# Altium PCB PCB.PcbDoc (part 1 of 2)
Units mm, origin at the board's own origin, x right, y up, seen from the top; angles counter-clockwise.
Board outline 92.39 x 84.17 mm, 2 copper layers (Top Layer, Bottom Layer); 172 components, 86 nets, 462 pads, 473 vias.
Unrouted connection lines stored in the file: 353.
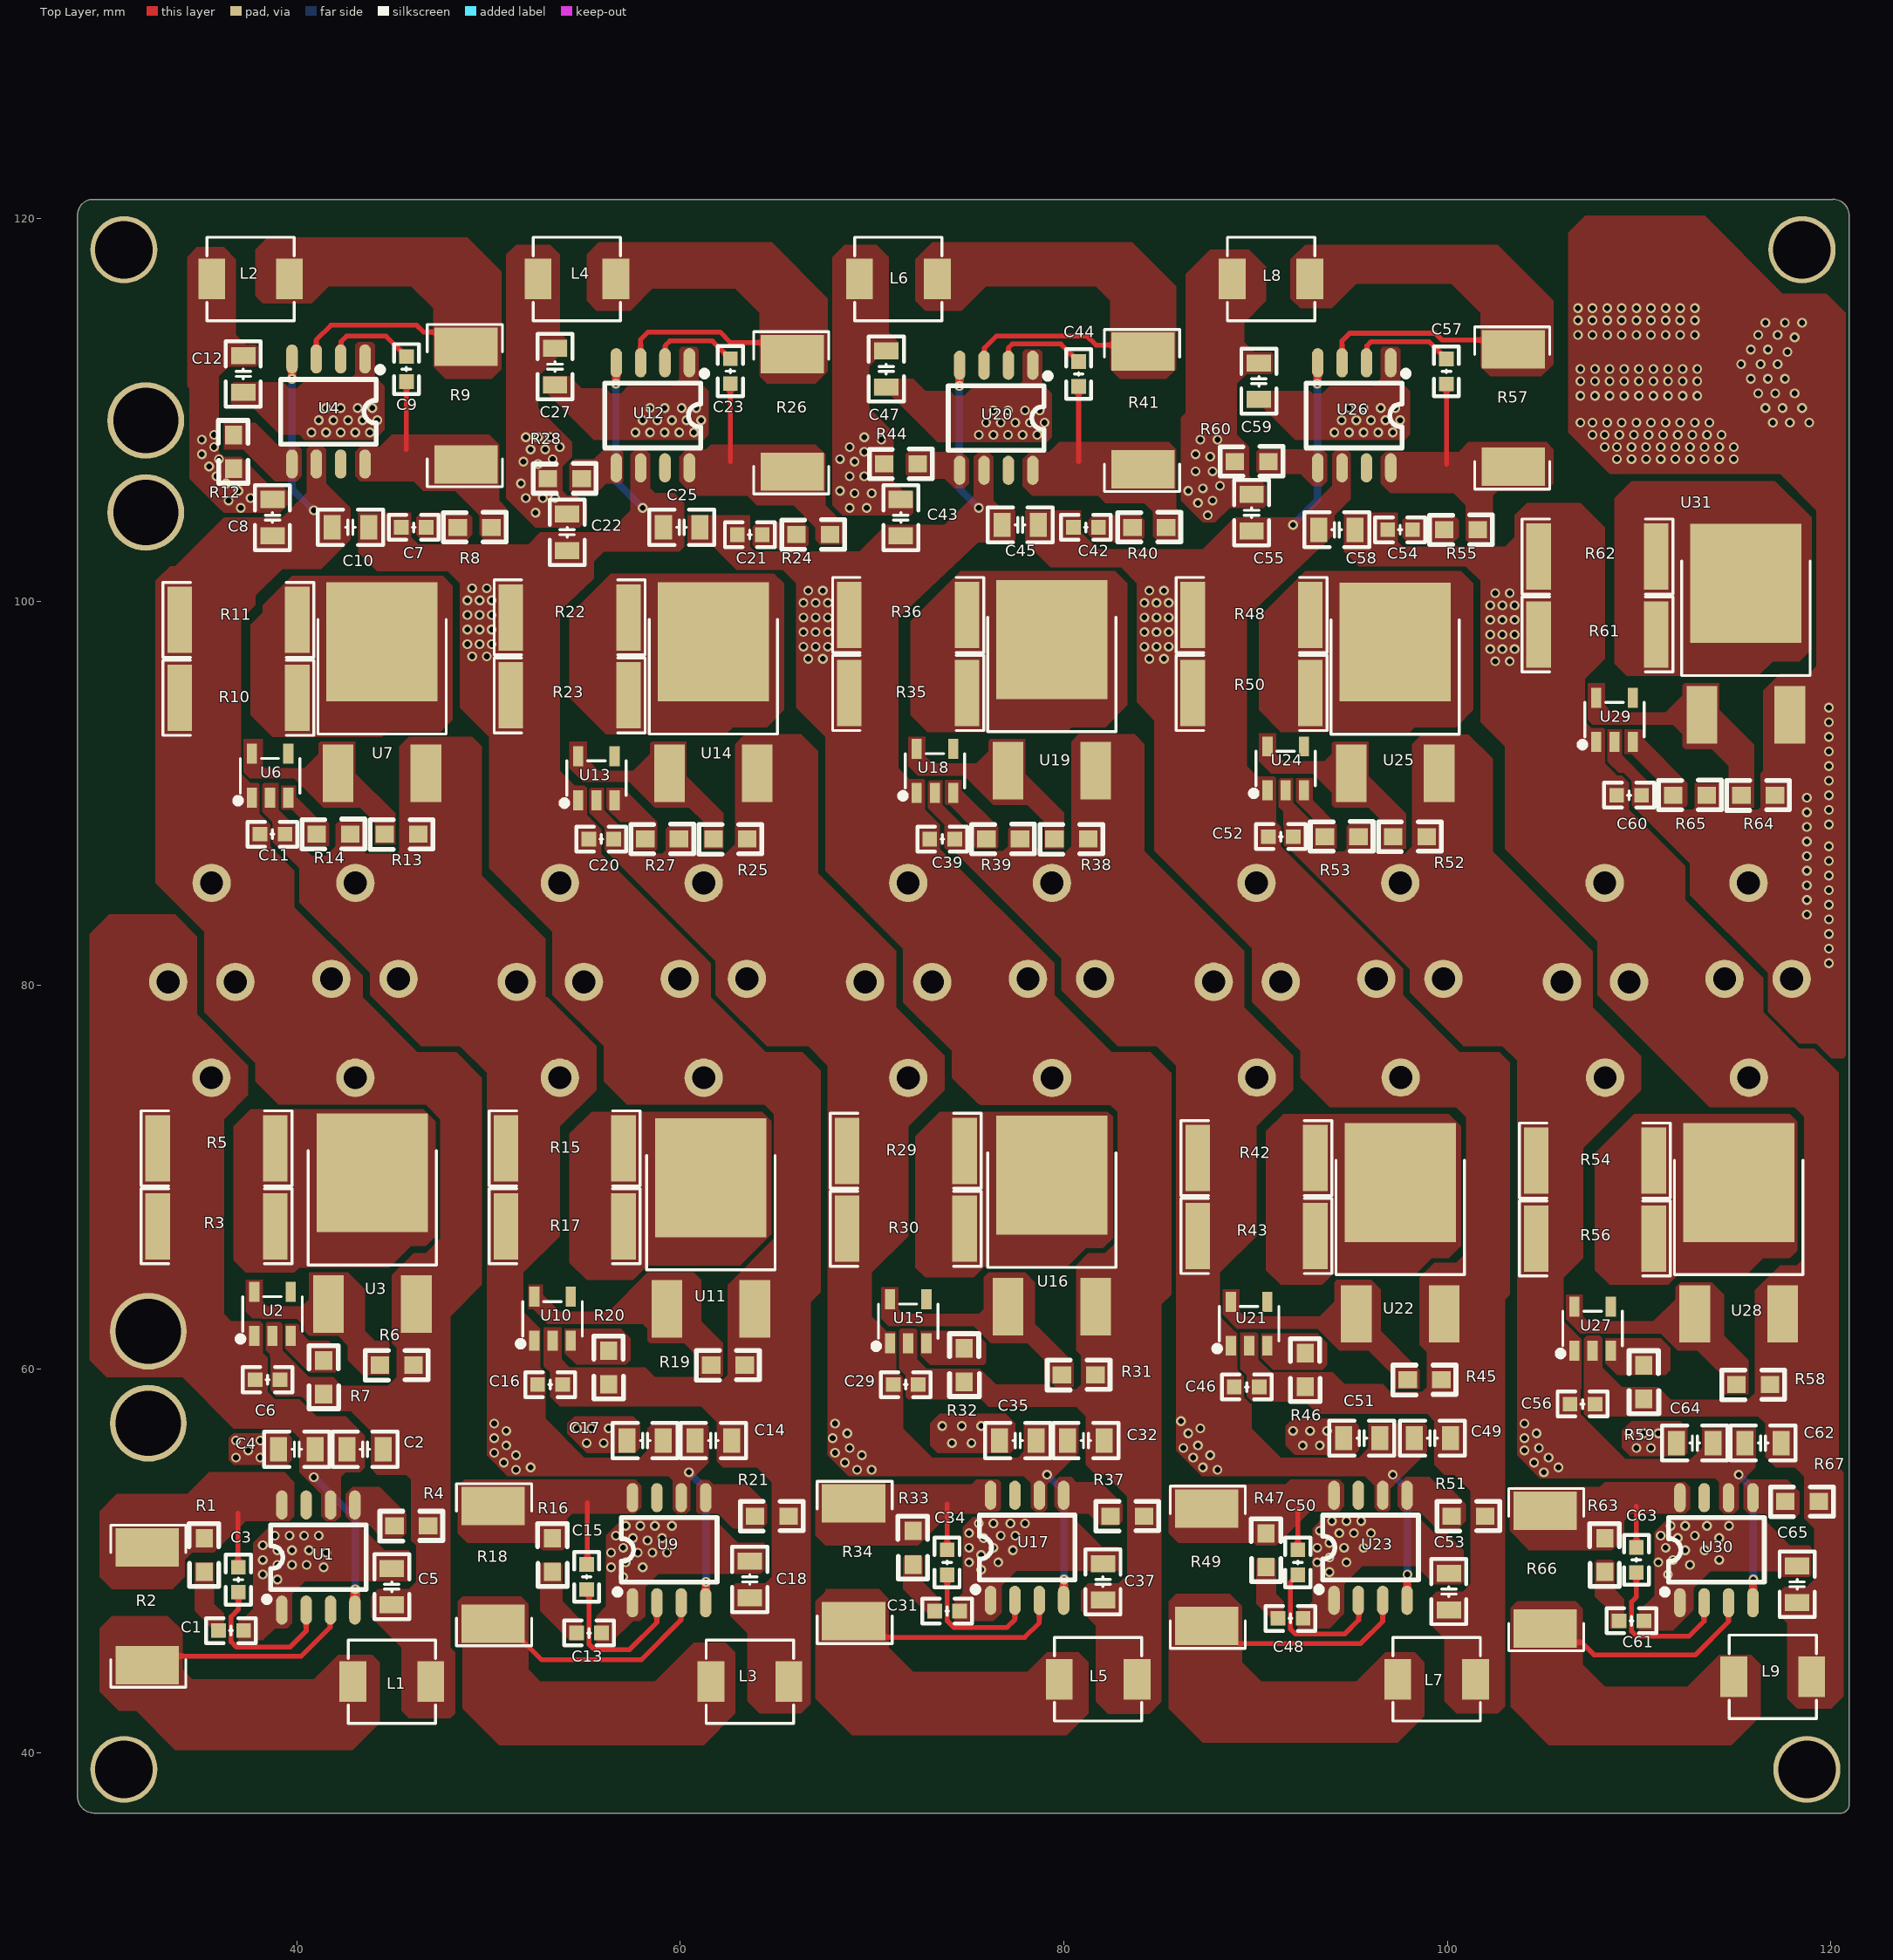
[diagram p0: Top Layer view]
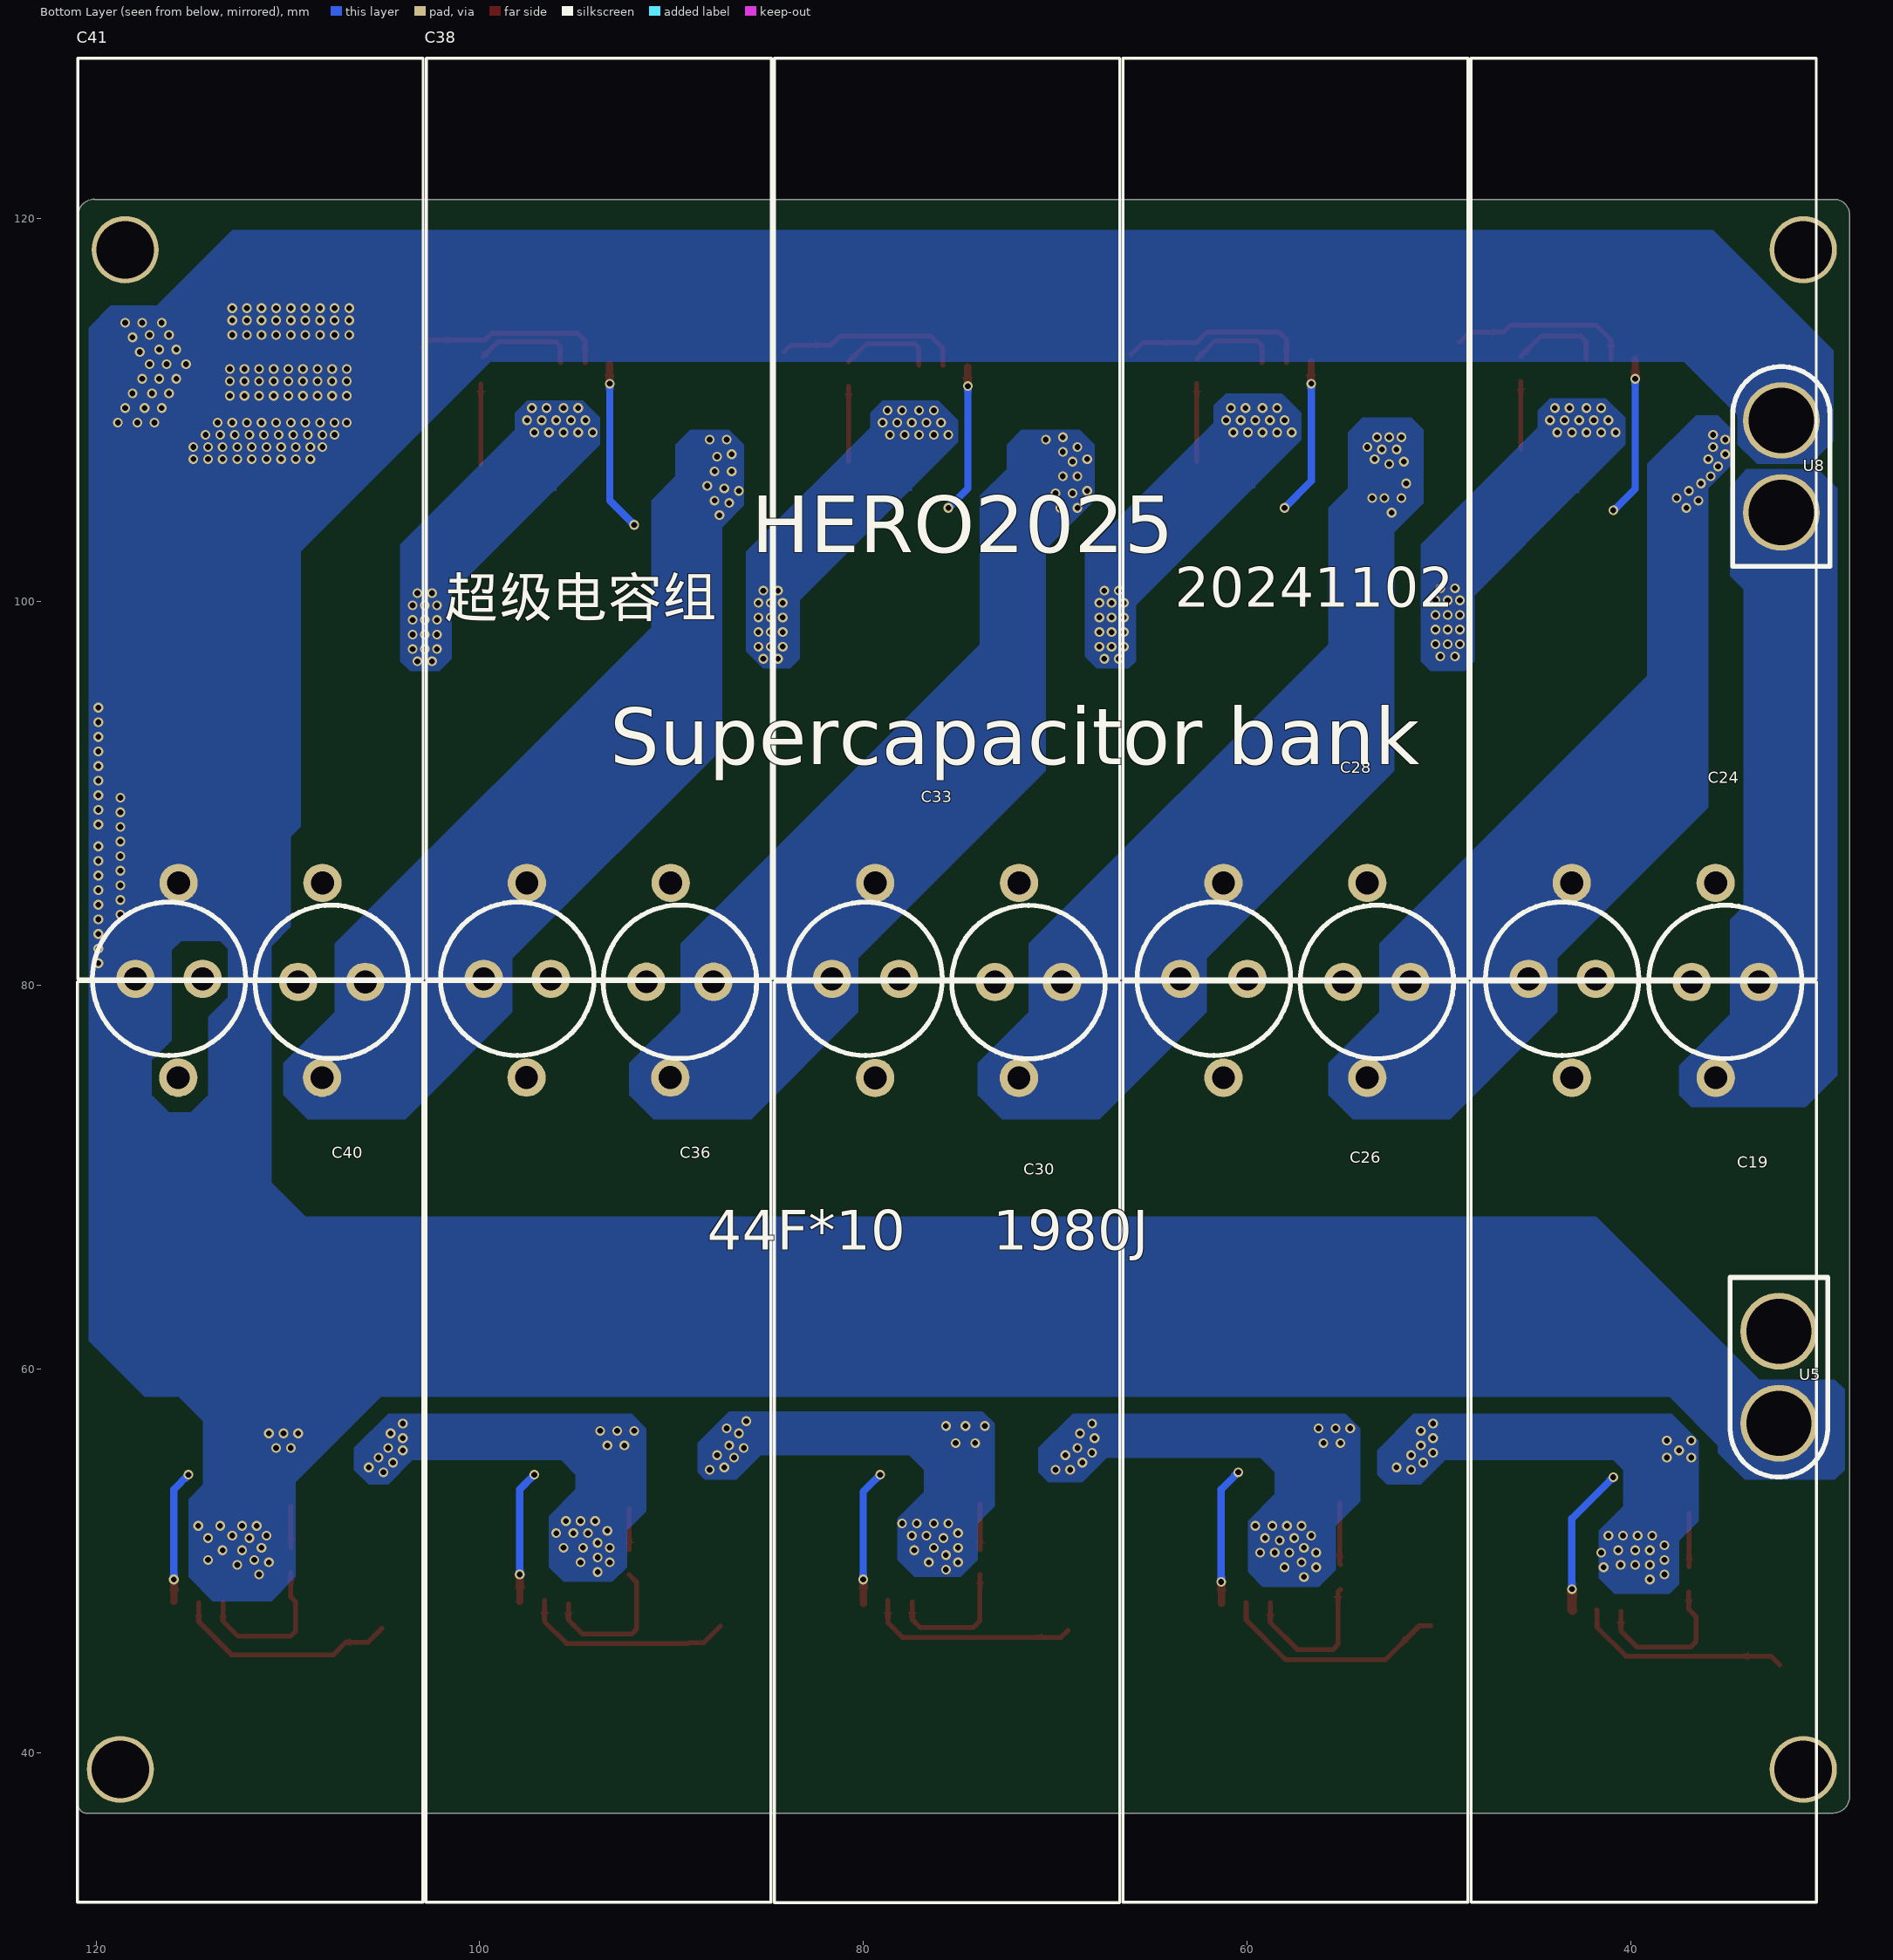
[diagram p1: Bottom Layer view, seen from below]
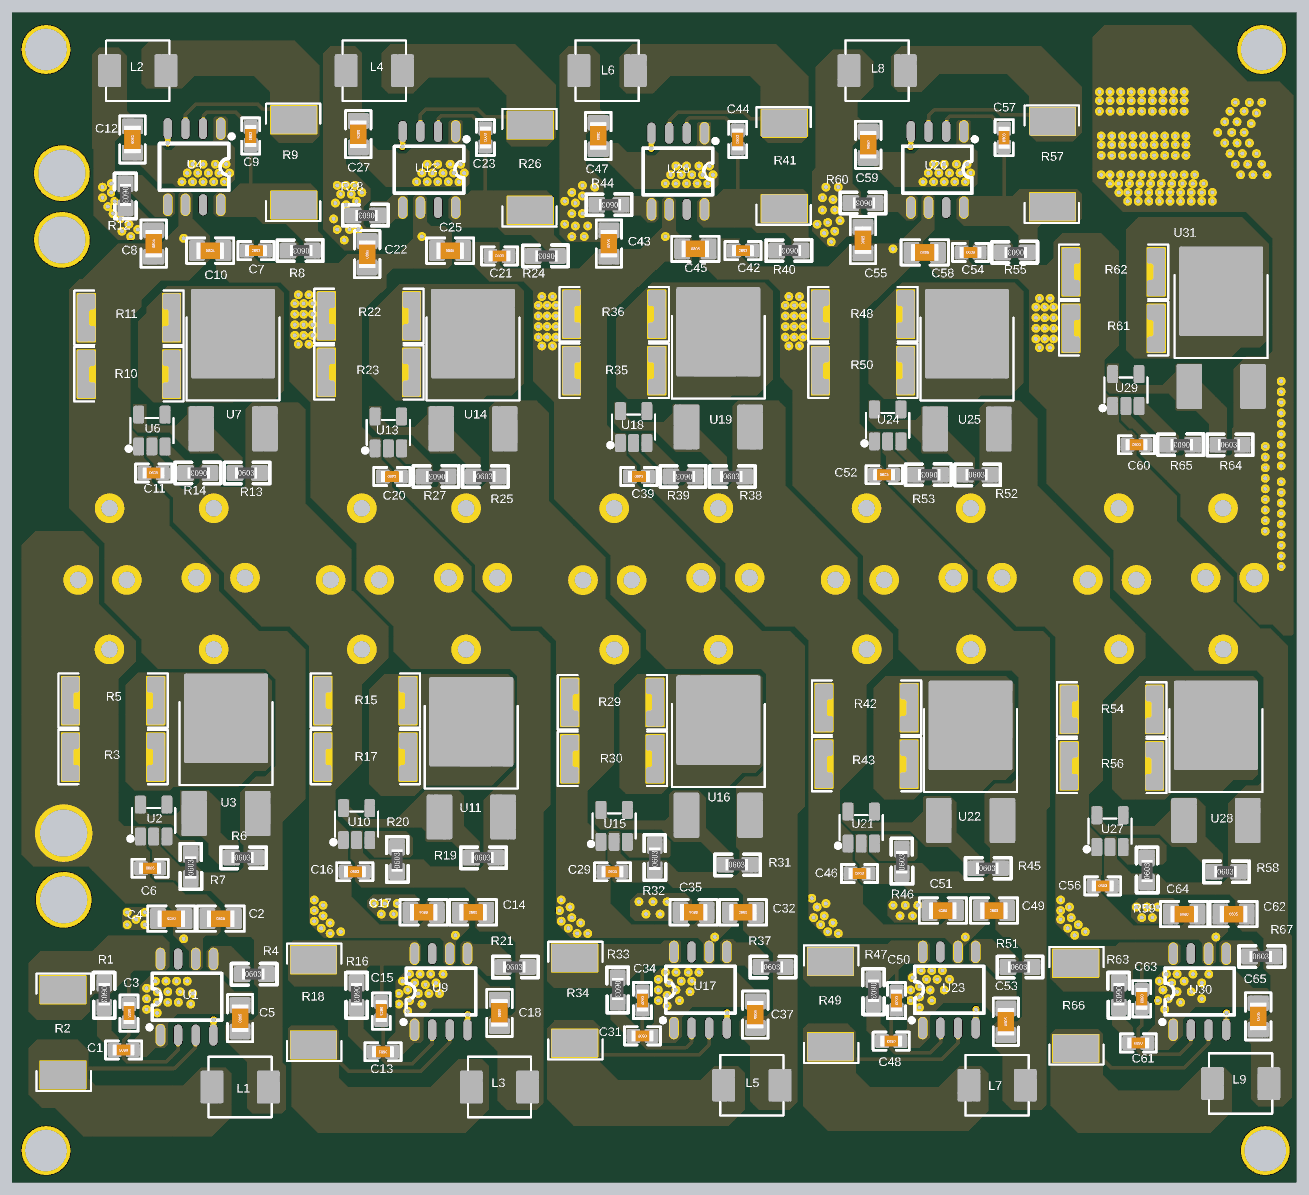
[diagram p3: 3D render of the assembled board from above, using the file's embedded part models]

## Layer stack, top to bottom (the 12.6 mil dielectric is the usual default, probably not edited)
Top Solder: solder mask 0.0102, Solder Resist, Dk 3.5
Top Layer: signal copper 0.0356
Dielectric 1: dielectric 0.32, FR-4, Dk 4.8
Bottom Layer: signal copper 0.0356
Bottom Solder: solder mask 0.0102, Solder Resist, Dk 3.5

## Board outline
28.57,37.731 28.57,120.188 28.575,120.142 cw(c29.377,120.186) 29.332,120.988 29.341,120.988 120.108,120.988 120.1,120.997 cw(c120.104,120.154) 120.946,120.158 120.953,120.189 120.961,37.319 cw(c120.468,37.32) 120.441,36.828 120.396,36.83 120.442,36.836 29.409,36.836 cw(c29.437,37.703)

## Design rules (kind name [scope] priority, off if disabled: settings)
Clearance [All] p1: gap=0.14 ignorepadtopadclearanceinfootprint=TRUE except(0.127: Arc-Arc Arc-Track Track-Track; 0.152: SMDPad-SMDPad SMDPad-THPad SMDPad-Via SMDPad-Fill SMDPad-Poly SMDPad-Region SMDPad-Text SMDPad-Hole THPad-THPad THPad-Via THPad-Fill THPad-Poly THPad-Region THPad-Text THPad-Hole Via-Via Via-Fill Via-Poly Via-Region Via-Text Via-Hole Fill-Hole Poly-Hole Region-Hole Text-Hole)
ComponentClearance [All] p1 off: gap=0.025 collisioncheckmode=3 verticalgap=0 showdistances=TRUE
DiffPairsRouting [All] p1: maxlimit=0.305 minlimit=0.203 mostfreqgap=0.254 toplayer_minwidth=0.203 toplayer_maxwidth=0.381 toplayer_prefwidth=0.254 bottomlayer_minwidth=0.203 bottomlayer_maxwidth=0.381 bottomlayer_prefwidth=0.254 maxuncoupledlength=12.7
HoleSize [All] p1: absolutevalues=TRUE maxlimit=40 minlimit=0.3 maxpercent=80.000 minpercent=20.000
MinimumSolderMaskSliver [All] p1: minsoldermaskwidth=0
NetAntennae [All] p1: netantennaetolerance=0.025
PasteMaskExpansion [All] p1: expansion=0.127
PlaneConnect [All] p1: planeconnectstyle=Direct reliefexpansion=0.508 reliefentries=4 reliefconductorwidth=0.635 reliefairgap=0.254
PolygonConnect [All] p1: connectstyle=Direct reliefconductorwidth=0.635 reliefentries=4 polygonreliefangle="90 Angle" airgapwidth=0.254
RoutingVias [All] p1: holewidth=0.508 width=0.889 viastyle="Through Hole" minholewidth=0.3 minwidth=0.6 maxholewidth=40 maxwidth=40.152
SilkToSilkClearance [All] p1: silktosilkclearance=0
SilkToSolderMaskClearance [IsPad] p1: minsilkscreentomaskgap=0 clearancetoexposedcopper=TRUE
SolderMaskExpansion [All] p1: expansion=0.064 istentingtop=FALSE
SupplyNets "Schematic Supply Nets_1" [InNet('GND')] p1: voltage=0.000
SupplyNets "Schematic Supply Nets" [InNet('PWR')] p2: voltage=0.000
Width [All] p1: maxlimit=3.175 minlimit=0.127 preferedwidth=0.508
21 further rules are at their usual default settings.

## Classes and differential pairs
component class "Room Definition5": C13 C14 C15 C16 C17 C18 L3 R15 R16 R17 R18 R19 R20 R21 U9 U10 U11
component class "Room Definition4": C20 C21 C22 C23 C25 C27 L4 R22 R23 R24 R25 R26 R27 R28 U12 U13 U14
component class "Room Definition3": C7 C8 C9 C10 C11 C12 L2 R8 R9 R10 R12 R13 R14 U4 U6 U7
component class "Room Definition2": C1 C2 C3 C4 C5 C6 L1 R1 R2 R3 R4 R5 R6 R7 U1 U2 U3
component class "Room Definition1": C1 C2 C3 C4 C5 L1 R1 R2 R4 U1

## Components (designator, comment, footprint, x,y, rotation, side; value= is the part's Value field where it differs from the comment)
C1 "2.2nF/0603" "C 0603_L" 36.576,46.355 r180 top
C2 "22uF/0805" "C 0805_L" 43.561,55.808 r0 top
C3 "100nF/0603" "C 0603_L" 36.957,49.007 r270 top
C4 "10uF/0805" "C 0805_L" 40.005,55.808 r180 top
C5 "22uF/0805" "C 0805_L" 44.958,48.641 r90 top
C6 "100nF/0603" "C 0603_L" 38.481,59.436 r0 top
C7 "2.2nF/0603" "C 0603_L" 46.101,103.886 r0 top
C8 "22uF/0805" "C 0805_L" 38.735,104.394 r90 top
C9 "100nF/0603" "C 0603_L" 45.72,112.141 r90 top
C10 "10uF/0805" "C 0805_L" 42.799,103.886 r0 top
C11 "100nF/0603" "C 0603_L" 38.735,87.884 r0 top
C12 "22uF/0805" "C 0805_L" 37.211,111.887 r270 top
C13 "2.2nF/0603" "C 0603_L" 55.245,46.228 r180 top
C14 "22uF/0805" "C 0805_L" 61.722,56.261 r0 top
C15 "100nF/0603" "C 0603_L" 55.118,49.149 r270 top
C16 "100nF/0603" "C 0603_L" 53.213,59.182 r0 top
C17 "10uF/0805" "C 0805_L" 58.166,56.261 r180 top
C18 "22uF/0805" "C 0805_L" 63.627,49.022 r90 top
C19 "3V/44F" cap 25.553,87.217 r0 bottom locked
C20 "100nF/0603" "C 0603_L" 55.88,87.63 r0 top
C21 "2.2nF/0603" "C 0603_L" 63.627,103.505 r0 top
C22 "22uF/0805" "C 0805_L" 54.102,103.632 r90 top
C23 "100nF/0603" "C 0603_L" 62.611,112.029 r90 top
C24 "3V/44F" cap 53.06,73.311 r180 bottom locked
C25 "10uF/0805" "C 0805_L" 60.071,103.886 r0 top
C26 "3V/44F" cap 43.721,87.217 r0 bottom locked
C27 "22uF/0805" "C 0805_L" 53.467,112.268 r270 top
C28 "3V/44F" cap 71.221,73.311 r180 bottom locked
C29 "100nF/0603" "C 0603_L" 71.755,59.182 r0 top
C30 "3V/44F" cap 61.887,87.205 r0 bottom locked
C31 "2.2nF/0603" "C 0603_L" 73.914,47.371 r180 top
C32 "22uF/0805" "C 0805_L" 81.153,56.261 r0 top
C33 "3V/44F" cap 89.382,73.311 r180 bottom locked
C34 "100nF/0603" "C 0603_L" 73.914,49.911 r270 top
C35 "10uF/0805" "C 0805_L" 77.597,56.261 r180 top
C36 "3V/44F" cap 80.064,87.222 r0 bottom locked
C37 "22uF/0805" "C 0805_L" 82.042,48.895 r90 top
C38 "3V/44F" cap 107.543,73.311 r180 bottom locked
C39 "100nF/0603" "C 0603_L" 73.66,87.63 r0 top
C40 "3V/44F" cap 98.225,87.219 r0 bottom locked
C41 "3V/44F" cap 125.704,73.311 r180 bottom locked
C42 "2.2nF/0603" "C 0603_L" 81.153,103.886 r0 top
C43 "22uF/0805" "C 0805_L" 71.501,104.394 r90 top
C44 "100nF/0603" "C 0603_L" 80.772,111.887 r90 top
C45 "10uF/0805" "C 0805_L" 77.724,104.013 r0 top
C46 "100nF/0603" "C 0603_L" 89.535,59.055 r0 top
C47 "22uF/0805" "C 0805_L" 70.739,112.141 r270 top
C48 "2.2nF/0603" "C 0603_L" 91.821,46.99 r180 top
C49 "22uF/0805" "C 0805_L" 99.218,56.388 r0 top
C50 "100nF/0603" "C 0603_L" 92.202,49.911 r270 top
C51 "10uF/0805" "C 0805_L" 95.535,56.388 r180 top
C52 "100nF/0603" "C 0603_L" 91.313,87.757 r0 top
C53 "22uF/0805" "C 0805_L" 100.076,48.387 r90 top
C54 "2.2nF/0603" "C 0603_L" 97.536,103.759 r0 top
C55 "22uF/0805" "C 0805_L" 89.789,104.648 r90 top
C56 "100nF/0603" "C 0603_L" 107.046,58.166 r0 top
C57 "100nF/0603" "C 0603_L" 99.949,112.014 r90 top
C58 "10uF/0805" "C 0805_L" 94.234,103.759 r0 top
C59 "22uF/0805" "C 0805_L" 90.17,111.506 r270 top
C60 "100nF/0603" "C 0603_L" 109.474,89.916 r0 top
C61 "2.2nF/0603" "C 0603_L" 109.601,46.863 r180 top
C62 "22uF/0805" "C 0805_L" 116.459,56.134 r0 top
C63 "100nF/0603" "C 0603_L" 109.855,50.038 r270 top
C64 "10uF/0805" "C 0805_L" 112.903,56.134 r180 top
C65 "22uF/0805" "C 0805_L" 118.237,48.768 r90 top
L1 "1uH" IND-SMD_L4.4-W4.2 44.958,43.688 r180 top
L2 "1uH" IND-SMD_L4.4-W4.2 37.592,116.84 r0 top
L3 "1uH" IND-SMD_L4.4-W4.2 63.627,43.688 r180 top
L4 "1uH" IND-SMD_L4.4-W4.2 54.61,116.84 r0 top
L5 "1uH" IND-SMD_L4.4-W4.2 81.788,43.815 r180 top
L6 "1uH" IND-SMD_L4.4-W4.2 71.374,116.84 r0 top
L7 "1uH" IND-SMD_L4.4-W4.2 99.441,43.815 r180 top
L8 "1uH" IND-SMD_L4.4-W4.2 90.805,116.84 r0 top
L9 "1uH" IND-SMD_L4.4-W4.2 116.967,43.942 r180 top
R1 "2.2/0603" "R 0603_L" 35.179,50.292 r270 top
R2 "100mΩ" RES-SMD_L6.4-W3.2-R2512 32.258,47.625 r270 top
R3 "4.7Ω/2512" R2512 35.814,67.437 r0 top value=4.7Ω
R4 "220/0603" "R 0603_L" 45.974,51.816 r0 top
R5 "4.7Ω/2512" R2512 35.814,71.501 r0 top value=4.7Ω
R6 "1k/0603" "R 0603_L" 45.212,60.198 r0 top
R7 "1k/0603" "R 0603_L" 41.402,59.563 r90 top
R8 "2.2/0603" "R 0603_L" 49.276,103.886 r180 top
R9 "100mΩ" RES-SMD_L6.4-W3.2-R2512 48.768,110.236 r90 top
R10 "4.7Ω/2512" R2512 36.957,94.996 r0 top value=4.7Ω
R11 "4.7Ω/2512" R2512 36.957,99.06 r0 top value=4.7Ω
R12 "220/0603" "R 0603_L" 36.703,107.823 r270 top
R13 "1k/0603" "R 0603_L" 45.466,87.884 r0 top
R14 "1k/0603" "R 0603_L" 41.91,87.884 r180 top
R15 "4.7Ω/2512" R2512 53.975,71.501 r0 top value=4.7Ω
R16 "2.2/0603" "R 0603_L" 53.34,50.292 r270 top
R17 "4.7Ω/2512" R2512 53.975,67.437 r0 top value=4.7Ω
R18 "100mΩ" RES-SMD_L6.4-W3.2-R2512 50.292,49.784 r270 top
R19 "1k/0603" "R 0603_L" 62.484,60.198 r0 top
R20 "1k/0603" "R 0603_L" 56.261,60.071 r90 top
R21 "220/0603" "R 0603_L" 64.77,52.324 r0 top
R22 "4.7Ω/2512" R2512 54.229,99.187 r0 top value=4.7Ω
R23 "4.7Ω/2512" R2512 54.229,95.123 r0 top value=4.7Ω
R24 "2.2/0603" "R 0603_L" 66.929,103.505 r180 top
R25 "1k/0603" "R 0603_L" 62.611,87.63 r0 top
R26 "100mΩ" RES-SMD_L6.4-W3.2-R2512 65.786,109.855 r90 top
R27 "1k/0603" "R 0603_L" 59.055,87.63 r180 top
R28 "220/0603" "R 0603_L" 53.975,106.426 r180 top
R29 "4.7Ω/2512" R2512 71.755,71.374 r0 top value=4.7Ω
R30 "4.7Ω/2512" R2512 71.755,67.31 r0 top value=4.7Ω
R31 "1k/0603" "R 0603_L" 80.772,59.69 r0 top
R32 "1k/0603" "R 0603_L" 74.803,60.198 r90 top
R33 "2.2/0603" "R 0603_L" 72.136,50.673 r270 top
R34 "100mΩ" RES-SMD_L6.4-W3.2-R2512 69.088,49.911 r270 top
R35 "4.7Ω/2512" R2512 71.882,95.25 r0 top value=4.7Ω
R36 "4.7Ω/2512" R2512 71.882,99.314 r0 top value=4.7Ω
R37 "220/0603" "R 0603_L" 83.312,52.324 r0 top
R38 "1k/0603" "R 0603_L" 80.391,87.63 r0 top
R39 "1k/0603" "R 0603_L" 76.835,87.63 r180 top
R40 "2.2/0603" "R 0603_L" 84.455,103.886 r180 top
R41 "100mΩ" RES-SMD_L6.4-W3.2-R2512 84.074,109.982 r90 top
R42 "4.7Ω/2512" R2512 90.043,70.993 r0 top value=4.7Ω
R43 "4.7Ω/2512" R2512 90.043,66.929 r0 top value=4.7Ω
R44 "220/0603" "R 0603_L" 71.501,107.188 r180 top
R45 "1k/0603" "R 0603_L" 98.806,59.436 r0 top
R46 "1k/0603" "R 0603_L" 92.583,59.944 r90 top
R47 "2.2/0603" "R 0603_L" 90.551,50.546 r270 top
R48 "4.7Ω/2512" R2512 89.789,99.314 r0 top value=4.7Ω
R49 "100mΩ" RES-SMD_L6.4-W3.2-R2512 87.503,49.657 r270 top
R50 "4.7Ω/2512" R2512 89.789,95.25 r0 top value=4.7Ω
R51 "220/0603" "R 0603_L" 101.092,52.324 r0 top
R52 "1k/0603" "R 0603_L" 98.044,87.757 r0 top
R53 "1k/0603" "R 0603_L" 94.488,87.757 r180 top
R54 "4.7Ω/2512" R2512 107.696,70.866 r0 top value=4.7Ω
R55 "2.2/0603" "R 0603_L" 100.711,103.759 r180 top
R56 "4.7Ω/2512" R2512 107.696,66.802 r0 top value=4.7Ω
R57 "100mΩ" RES-SMD_L6.4-W3.2-R2512 103.378,110.109 r90 top
R58 "1k/0603" "R 0603_L" 115.951,59.182 r0 top
R59 "1k/0603" "R 0603_L" 110.236,59.309 r90 top
R60 "220/0603" "R 0603_L" 89.789,107.315 r180 top
R61 "4.7Ω/2512" R2512 107.823,98.298 r0 top value=4.7Ω
R62 "4.7Ω/2512" R2512 107.823,102.362 r0 top value=4.7Ω
R63 "2.2/0603" "R 0603_L" 108.204,50.292 r270 top
R64 "1k/0603" "R 0603_L" 116.205,89.916 r0 top
R65 "1k/0603" "R 0603_L" 112.649,89.916 r180 top
R66 "100mΩ" RES-SMD_L6.4-W3.2-R2512 105.156,49.53 r270 top
R67 "220/0603" "R 0603_L" 118.491,53.086 r0 top
U1 "ETA3006S8A" SOIC-8_L5.0-W4.0-P1.27-LS6.0-TL 41.021,50.165 r90 top
U2 "BW6103" TSOT-23-5_L2.9-W1.6-P0.95-LS2.8-BL 38.735,62.865 r0 top
U3 "20N04" TO-252-2_L6.6-W6.1-P4.57-LS9.9-BR-CW 43.942,66.802 r270 top
U4 "ETA3006S8A" SOIC-8_L5.0-W4.0-P1.27-LS6.0-TL 41.763,109.928 r270 top
U5 "XT30U-F" CONN-TH_XT30U-F 32.258,59.563 r270 bottom
U6 "BW6103" TSOT-23-5_L2.9-W1.6-P0.95-LS2.8-BL 38.608,90.932 r0 top
U7 "20N04" TO-252-2_L6.6-W6.1-P4.57-LS9.9-BR-CW 44.45,94.488 r270 top
U8 "XT30U-F" CONN-TH_XT30U-F 32.131,107.061 r90 bottom
U9 "ETA3006S8A" SOIC-8_L5.0-W4.0-P1.27-LS6.0-TL 59.309,50.546 r90 top
U10 "BW6103" TSOT-23-5_L2.9-W1.6-P0.95-LS2.8-BL 53.34,62.611 r0 top
U11 "20N04" TO-252-2_L6.6-W6.1-P4.57-LS9.9-BR-CW 61.595,66.548 r270 top
U12 "ETA3006S8A" SOIC-8_L5.0-W4.0-P1.27-LS6.0-TL 58.674,109.728 r270 top
U13 "BW6103" TSOT-23-5_L2.9-W1.6-P0.95-LS2.8-BL 55.626,90.805 r0 top
U14 "20N04" TO-252-2_L6.6-W6.1-P4.57-LS9.9-BR-CW 61.722,94.488 r270 top
U15 "BW6103" TSOT-23-5_L2.9-W1.6-P0.95-LS2.8-BL 71.882,62.484 r0 top
U16 "20N04" TO-252-2_L6.6-W6.1-P4.57-LS9.9-BR-CW 79.375,66.675 r270 top
U17 "ETA3006S8A" SOIC-8_L5.0-W4.0-P1.27-LS6.0-TL 77.978,50.673 r90 top
U18 "BW6103" TSOT-23-5_L2.9-W1.6-P0.95-LS2.8-BL 73.279,91.186 r0 top
U19 "20N04" TO-252-2_L6.6-W6.1-P4.57-LS9.9-BR-CW 79.375,94.615 r270 top
U20 "ETA3006S8A" SOIC-8_L5.0-W4.0-P1.27-LS6.0-TL 76.581,109.601 r270 top
U21 "BW6103" TSOT-23-5_L2.9-W1.6-P0.95-LS2.8-BL 89.662,62.357 r0 top
U22 "20N04" TO-252-2_L6.6-W6.1-P4.57-LS9.9-BR-CW 97.536,66.294 r270 top
U23 "ETA3006S8A" SOIC-8_L5.0-W4.0-P1.27-LS6.0-TL 95.885,50.673 r90 top
U24 "BW6103" TSOT-23-5_L2.9-W1.6-P0.95-LS2.8-BL 91.567,91.313 r0 top
U25 "20N04" TO-252-2_L6.6-W6.1-P4.57-LS9.9-BR-CW 97.278,94.483 r270 top
U26 "ETA3006S8A" SOIC-8_L5.0-W4.0-P1.27-LS6.0-TL 95.25,109.728 r270 top
U27 "BW6103" TSOT-23-5_L2.9-W1.6-P0.95-LS2.8-BL 107.569,62.103 r0 top
U28 "20N04" TO-252-2_L6.6-W6.1-P4.57-LS9.9-BR-CW 115.189,66.294 r270 top
U29 "BW6103" TSOT-23-5_L2.9-W1.6-P0.95-LS2.8-BL 108.712,93.853 r0 top
U30 "ETA3006S8A" SOIC-8_L5.0-W4.0-P1.27-LS6.0-TL 113.919,50.546 r90 top
U31 "20N04" TO-252-2_L6.6-W6.1-P4.57-LS9.9-BR-CW 115.57,97.536 r270 top

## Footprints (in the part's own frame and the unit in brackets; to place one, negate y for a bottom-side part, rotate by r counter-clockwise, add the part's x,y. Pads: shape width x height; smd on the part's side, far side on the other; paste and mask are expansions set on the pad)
"C 0603_L" [mil] "无极性贴片电容"
  rect 30x30 smd: 1(-25.59,0) 2(25.59,0)
  silkscreen extent -51,-26 51,26, body extent -31,-16 31,16, height 32
"C 0805_L" [mil] "无极性贴片电容"
  rect 35x50 smd: 1(-37.4,0) 2(37.4,0)
  silkscreen extent -67,-36 67,36, body extent -39,-24 39,24, height 20
cap [mm]
  round 2 hole 1.2: 1(10,12.033) 2(17.5,12.033) 3(7.75,7.033) 4(11.25,7.033)
  silkscreen extent 4.75,3.03 22.75,55.03
CONN-TH_XT30U-F [mm]
  round 4 hole 3.4: 1(2.4,0) 2(-2.4,0)
  silkscreen extent -5.21,-2.54 5.2,2.54
IND-SMD_L4.4-W4.2 [mm]
  rect 1.4x2.12 smd: 1(2.028,0) 2(-2.028,0)
  silkscreen extent -2.28,-2.18 2.28,2.18
R2512 [mm]
  rect 1.283x3.456 smd paste-100 mask+0.051: 1(-3.066,0) 2(3.066,0)
  silkscreen extent -3.94,-1.96 3.94,1.96
"R 0603_L" [mil] "1/10W"
  rect 38x35 smd: 1(-34.5,0) 2(34.5,0)
  silkscreen extent -64,-31 64,30, body extent -34,-16 29,16, height 18
RES-SMD_L6.4-W3.2-R2512 [mm]
  rect 2x3.3 smd paste+0 mask+0.051: 1(-3.066,-0.052) 2(3.066,-0.052)
  silkscreen extent -4.23,-1.96 4.23,1.96
SOIC-8_L5.0-W4.0-P1.27-LS6.0-TL [mm]
  oval 1.52x0.6 smd paste+0 mask+0.051: 1(-2.74,1.798) 2(-2.74,0.528) 3(-2.74,-0.742) 4(-2.74,-2.012) 5(2.74,-2.012) 6(2.74,-0.742) 7(2.74,0.528) 8(2.74,1.798)
  silkscreen extent -2.33,-2.61 1.7,2.73
TO-252-2_L6.6-W6.1-P4.57-LS9.9-BR-CW [mm]
  rect 3x1.6 smd: 1(3.424,-2.29) 3(3.424,2.29)
  rect 6.2x5.8 smd: 2(-3.424,0)
  silkscreen extent -4.58,-3.35 1.38,3.35
TSOT-23-5_L2.9-W1.6-P0.95-LS2.8-BL [mm]
  rect 0.532x1.045 smd: 1(-0.95,-1.147) 2(0,-1.147) 3(0.95,-1.147) 4(0.95,1.147) 5(-0.95,1.147)
  silkscreen extent -1.82,-1.45 1.55,0.9

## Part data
C1 C2 C3 C4 C5 C6 C7 C8 C9 C10 C11 C12 C13 C14 C15 C16 C17 C18 C20 C21 C22 C23 C25 C27 C29 C31 C32 C34 C35 C37 C39 C42 C43 C44 C45 C46 C47 C48 C49 C50 C51 C52 C53 C54 C55 C56 C57 C58 C59 C60 C61 C62 C63 C64 C65: library part CAP, "陶瓷电容"
C19 C24 C26 C28 C30 C33 C36 C38 C40 C41: library part "3V 44F", "3V 40F 超级电容"
L1 L2 L3 L4 L5 L6 L7 L8 L9: library part FXL0420-1R0-M
R1 R4 R6 R7 R8 R12 R13 R14 R16 R19 R20 R21 R24 R25 R27 R28 R31 R32 R33 R37 R38 R39 R40 R44 R45 R46 R47 R51 R52 R53 R55 R58 R59 R60 R63 R64 R65 R67: library part RES, "贴片电阻"
R2 R9 R18 R26 R34 R41 R49 R57 R66: library part HOJLR2512-3W-100MR-1%
R3 R5 R10 R11 R15 R17 R22 R23 R29 R30 R35 R36 R42 R43 R48 R50 R54 R56 R61 R62: library part WF25P4R70FTL, "4.7Ω 2W", JLCPCB Part Class="Extended Part", LCSC Part Name="4.7Ω ±1% 2W", Manufacturer=Walsin(华新科), Operating Temperature Range=-55℃~+155℃, Overload Voltage (Max)=300V, Power(Watts)=2W, Temperature Coefficient=±100ppm/℃, Tolerance=±1%
U2 U6 U10 U13 U15 U18 U21 U24 U27 U29: "3V 均压保护芯片"
U3 U7 U11 U14 U16 U19 U22 U25 U28 U31: "40V 20A", Continuous Drain Current (Id)=20A, Drain Source On Resistance (RDS(on)@Vgs,Id)=25mΩ, Drain Source Voltage (Vdss)=40V, Gate Threshold Voltage (Vgs(th)@Id)=2.2V, LCSC Part Name="1个N沟道 耐压:40V 电流:20A", Manufacturer=HL(富海微)
U5 U8: Colour=黄色, contact resistance=-, JLCPCB Part Class="Extended Part", LCSC Part Name="AMASS(艾迈斯)轻量版锂电池插头母头 XT30U-F", Manufacturer=AMASS(艾迈斯)

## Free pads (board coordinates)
  round 3.5 hole 3: 7(30.988,39.116) 7(30.988,118.364) 7(118.491,118.364) 7(118.745,39.116)

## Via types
v1: diameter 0.508, hole 0.305, Top Layer to Bottom Layer, 473 vias

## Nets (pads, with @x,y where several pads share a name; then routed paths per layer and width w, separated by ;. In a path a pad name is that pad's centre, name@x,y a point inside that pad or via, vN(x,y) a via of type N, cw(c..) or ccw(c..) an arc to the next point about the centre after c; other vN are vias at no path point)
GND: C41.1 C41.3 C60.2 C61.1 C64.2 C65.2 R64.2 R65.1 U5.1 U8.1 U29.2 U30.1 U31.3
  other v1: 111.506,49.276 112.649,49.784 110.998,49.911 111.76,50.038 114.173,50.038 112.395,50.546 113.411,50.546 111.379,50.673 112.014,51.181 114.173,51.181 111.125,51.308 112.903,51.308 111.633,51.816 112.395,51.816 113.538,51.816 114.681,51.816 109.855,55.88 110.617,55.88 109.474,56.642 110.236,56.642 110.998,56.642 119.888,81.153 119.888,81.915 119.888,82.677 119.888,83.439 118.745,83.693 119.888,84.201 118.745,84.455 119.888,84.963 118.745,85.217 119.888,85.725 118.745,85.979 119.888,86.487 118.745,86.741 119.888,87.249 118.745,87.503 118.745,88.265 119.888,88.392 118.745,89.027 119.888,89.154 118.745,89.789 119.888,89.916 119.888,90.678 119.888,91.44 119.888,92.202 119.888,92.964 119.888,93.726 119.888,94.488 108.839,107.442 109.601,107.442 110.363,107.442 111.125,107.442 111.887,107.442 112.649,107.442 113.411,107.442 114.173,107.442 114.935,107.442 108.204,108.077 108.839,108.077 109.601,108.077 110.363,108.077 111.125,108.077 111.887,108.077 112.649,108.077 113.411,108.077 114.173,108.077 114.935,108.077 107.569,108.712 108.204,108.712 108.966,108.712 109.728,108.712 110.49,108.712 111.252,108.712 112.014,108.712 112.776,108.712 113.538,108.712 114.3,108.712 106.934,109.347 107.569,109.347 108.331,109.347 109.093,109.347 109.855,109.347 110.617,109.347 111.379,109.347 112.141,109.347 112.903,109.347 113.665,109.347 116.967,109.347 117.856,109.347 118.872,109.347 116.586,110.109 117.475,110.109 118.491,110.109 106.934,110.744 107.696,110.744 108.458,110.744 109.22,110.744 109.982,110.744 110.744,110.744 111.506,110.744 112.268,110.744 113.03,110.744 116.205,110.871 117.094,110.871 118.11,110.871 106.934,111.506 107.696,111.506 108.458,111.506 109.22,111.506 109.982,111.506 110.744,111.506 111.506,111.506 112.268,111.506 113.03,111.506 115.824,111.633 116.713,111.633 117.602,111.633 106.934,112.141 107.696,112.141 108.458,112.141 109.22,112.141 109.982,112.141 110.744,112.141 111.506,112.141 112.268,112.141 113.03,112.141 115.316,112.395 116.332,112.395 117.221,112.395 117.729,113.03 115.824,113.157 116.713,113.157 118.11,113.792 106.807,113.919 107.569,113.919 108.331,113.919 109.093,113.919 109.855,113.919 110.617,113.919 111.379,113.919 112.141,113.919 112.903,113.919 116.205,113.919 117.221,113.919 116.586,114.554 117.602,114.554 118.491,114.554 106.807,114.681 107.569,114.681 108.331,114.681 109.093,114.681 109.855,114.681 110.617,114.681 111.379,114.681 112.141,114.681 112.903,114.681 106.807,115.316 107.569,115.316 108.331,115.316 109.093,115.316 109.855,115.316 110.617,115.316 111.379,115.316 112.141,115.316 112.903,115.316
NetC1_2: C1.2 R1.2
NetC3_1: C3.1 R1.1 R2.1 U1.8 | length 2.8
  Top Layer w0.254: C3.1@36.942,49.672 36.942,52.481
NetC3_2: C3.2 U1.2 | length 8.1
  Top Layer w0.254: C3.2@36.957,48.357 36.957,47.462 36.578,47.083 36.578,45.772 36.855,45.495 39.655,45.495 40.495,46.335 U1.2@40.495,47.353
NetC7_2: C7.2 R8.2
NetC9_1: C9.1 R8.1 R9.1 U4.8 | length 3.5
  Top Layer w0.254: 45.72,107.95 C9.1@45.72,111.491
NetC9_2: C9.2 U4.2 | length 4.9
  Top Layer w0.254: U4.2@42.291,112.668 42.309,112.686 42.309,113.573 42.595,113.858 44.657,113.858 45.466,113.049 45.466,113.045 45.716,112.795 C9.2@45.72,112.795
NetC13_2: C13.2 R16.2
NetC15_1: C15.1 R16.1 R18.1 U9.8 | length 3.2
  Top Layer w0.254: C15.1@55.118,49.799 55.161,49.842 55.161,53.023
NetC15_2: C15.2 U9.2 | length 8.2
  Top Layer w0.254: C15.2@55.118,48.499 55.244,48.373 55.244,45.633 55.52,45.357 57.354,45.357 58.78,46.784 U9.2@58.781,47.806
NetC21_2: C21.2 R24.2
NetC23_1: C23.1 R24.1 R26.1 U12.8 | length 4.1
  Top Layer w0.254: 62.611,107.315 C23.1@62.611,111.379
NetC23_2: C23.2 U12.2 | length 4.8
  Top Layer w0.254: U12.2@59.202,112.468 59.215,112.482 59.215,113.37 59.453,113.607 61.667,113.607 62.341,112.933 62.357,112.933 62.595,112.695 C23.2@62.595,112.679
NetC31_2: C31.2 R33.2
NetC34_1: C34.1 R33.1 R34.1 U17.8 | length 2.4
  Top Layer w0.254: C34.1@73.914,50.561 73.914,52.959
NetC34_2: C34.2 U17.2 | length 7.2
  Top Layer w0.254: C34.2@73.914,49.261 73.916,49.259 73.916,46.861 74.258,46.519 77.043,46.519 77.45,46.926 U17.2@77.45,47.859
NetC42_2: C42.2 R40.2
NetC44_1: C44.1 R40.1 R41.1 U20.8 | length 3.9
  Top Layer w0.254: 80.772,107.315 C44.1@80.772,111.237
NetC44_2: C44.2 U20.2 | length 5
  Top Layer w0.254: U20.2@77.1,112.35 77.113,112.363 77.113,113.252 77.309,113.448 79.846,113.448 80.503,112.791 80.518,112.791 C44.2@80.772,112.537 C44.2@80.772,112.522
NetC48_2: C48.2 R47.2
NetC50_1: C50.1 R47.1 R49.1 U23.8 | length 2.1
  Top Layer w0.254: C50.1@92.202,50.561 92.202,52.705
NetC50_2: C50.2 U23.2 | length 7.8
  Top Layer w0.254: C50.2@92.202,49.261 91.823,48.883 91.823,46.427 92.082,46.168 94.636,46.168 95.377,46.908 U23.2@95.377,47.752
NetC54_2: C54.2 R55.2
NetC57_1: C57.1 R55.1 R57.1 U26.8 | length 4.2
  Top Layer w0.254: 99.949,107.188 C57.1@99.949,111.364
NetC57_2: C57.2 U26.2 | length 5.3
  Top Layer w0.254: U26.2@95.778,112.468 95.807,112.497 95.807,113.354 96.022,113.569 99.044,113.569 C57.2@99.837,112.776
NetC61_2: C61.2 R63.2
NetC63_1: C63.1 R63.1 R66.1 U30.8 | length 2.1
  Top Layer w0.254: C63.1@109.855,50.688 109.855,52.832
NetC63_2: C63.2 U30.2 | length 8.4
  Top Layer w0.254: C63.2@109.855,49.388 109.855,48.108 109.603,47.857 109.603,46.321 109.871,46.053 112.601,46.053 113.387,46.84 113.387,47.802 U30.2@113.391,47.806
NetL1_1: L1.1 R2.2 U1.3 | length 11.3
  Top Layer w0.254: R2.2@32.206,44.559 32.669,45.021 40.236,45.021 41.744,46.529 41.744,47.406 U1.3@41.763,47.425
NetL2_1: L2.1 R9.2 U4.3 | length 9.6
  Top Layer w0.254: U4.3@41.021,112.668 41.021,113.665 41.783,114.427 46.258,114.427 46.615,114.07 48.363,114.07 R9.2@48.895,113.538
NetL3_1: L3.1 R18.2 U9.3 | length 12.1
  Top Layer w0.254: R18.2@50.419,46.609 50.999,46.609 52.777,44.831 57.967,44.831 60.039,46.903 60.039,47.794 U9.3@60.051,47.806
NetL4_1: L4.1 R26.2 U12.3 | length 10
  Top Layer w0.254: U12.3@57.932,112.468 57.932,113.685 58.319,114.072 62.077,114.072 62.63,113.519 65.424,113.519 R26.2@66.04,112.903
NetL5_1: L5.1 R34.2 U17.3 | length 11
  Top Layer w0.254: R34.2@69.342,46.355 69.701,45.996 77.96,45.996 78.72,46.756 U17.3@78.72,47.933
NetL6_1: L6.1 R41.2 U20.3 | length 9.8
  Top Layer w0.254: U20.3@75.839,112.341 75.859,112.361 75.859,113.236 76.479,113.856 81.216,113.856 81.679,113.393 83.781,113.393 R41.2@84.126,113.048
NetL7_1: L7.1 R49.2 U23.3 | length 11.1
  Top Layer w0.254: R49.2@87.451,46.591 88.324,45.718 89.087,45.718 89.123,45.682 95.477,45.682 96.627,46.832 U23.3@96.627,47.933
NetL8_1: L8.1 R57.2 U26.3 | length 10.1
  Top Layer w0.254: U26.3@94.508,112.468 94.508,113.611 94.909,114.011 99.364,114.011 99.719,113.656 102.625,113.656 R57.2@102.997,113.284
NetL9_1: L9.1 R66.2 U30.3 | length 11.8
  Top Layer w0.254: R66.2@105.104,46.464 105.822,45.747 106.987,45.747 107.648,45.085 112.927,45.085 114.657,46.815 U30.3@114.657,47.802
NetR3_2: R3.2 R5.2 U3.2
NetR4_1: R4.1 U1.5
NetR6_1: R6.1 U2.5 U3.1
NetR7_2: R7.2 U2.3
NetR10_2: R10.2 R11.2 U7.2
NetR12_1: R12.1 U4.5
NetR13_1: R13.1 U6.5 U7.1
NetR14_2: R14.2 U6.3
NetR15_2: R15.2 R17.2 U11.2
NetR19_1: R19.1 U10.5 U11.1
NetR20_2: R20.2 U10.3
NetR21_1: R21.1 U9.5
NetR22_2: R22.2 R23.2 U14.2
NetR25_1: R25.1 U13.5 U14.1
NetR27_2: R27.2 U13.3
NetR28_1: R28.1 U12.5
NetR29_2: R29.2 R30.2 U16.2
NetR31_1: R31.1 U15.5 U16.1
NetR32_2: R32.2 U15.3
NetR35_2: R35.2 R36.2 U19.2
NetR37_1: R37.1 U17.5
NetR38_1: R38.1 U18.5 U19.1
NetR39_2: R39.2 U18.3
NetR42_2: R42.2 R43.2 U22.2
NetR44_1: R44.1 U20.5
NetR45_1: R45.1 U21.5 U22.1
NetR46_2: R46.2 U21.3
NetR48_2: R48.2 R50.2 U25.2
NetR51_1: R51.1 U23.5
NetR52_1: R52.1 U24.5 U25.1
NetR53_2: R53.2 U24.3
NetR54_2: R54.2 R56.2 U28.2
NetR58_1: R58.1 U27.5 U28.1
NetR59_2: R59.2 U27.3
NetR60_1: R60.1 U26.5
NetR61_2: R61.2 R62.2 U31.2
NetR64_1: R64.1 U29.5 U31.1
NetR65_2: R65.2 U29.3
NetR67_1: R67.1 U30.5
P2: C2.2 C5.1 C6.2 C8.1 C10.1 C11.1 C19.2 C19.4 C24.2 C24.4 L1.2 R4.2 R6.2 R7.1 R10.1 R11.1 U2.2 U3.3 U4.4 U4.6 U6.1 | length 8.3
  Top Layer w0.381: v1(39.751,111.633) U4.4@39.751,112.649
  Bottom Layer w0.381: v1(39.751,111.633) 39.751,105.886 v1@40.862,104.775
  other v1: 40.894,104.775
P3: C1.1 C4.2 C5.2 C8.2 C11.2 C12.1 C14.1 C16.1 C17.1 C24.1 C24.3 C26.1 C26.3 L2.2 R12.2 R13.2 R14.1 R15.1 R17.1 U1.1 U6.2 U7.3 U9.4 U9.6 U10.1 | length 7.2
  Top Layer w0.381: U9.4@61.331,47.762 61.331,48.885 v1(61.341,48.895)
  Bottom Layer w0.381: v1(60.452,54.61) 61.341,53.721 v1(61.341,48.895)
  other v1: 38.989,49.022 38.227,49.276 41.402,49.657 38.989,49.784 39.751,49.784 40.513,49.784 38.227,50.038 41.529,50.419 38.989,50.546 39.751,50.546 40.64,50.546 38.227,50.8 38.862,51.308 39.624,51.308 40.386,51.308 41.148,51.308 51.435,54.737 52.197,54.864 50.8,55.118 36.83,55.372 38.1,55.372 51.435,55.499 50.292,55.626 37.465,55.753 50.927,56.007 36.83,56.261 38.1,56.261 50.292,56.388 50.927,56.769 50.292,57.15 37.084,104.902 36.449,105.283 37.592,105.41 36.957,105.791 36.322,106.172 35.814,106.553 35.433,107.061 35.941,107.442 35.052,107.696 35.687,108.077 35.052,108.458 35.687,108.712
P4: C7.1 C10.2 C12.2 C14.2 C16.2 C18.1 C20.1 C22.1 C25.1 C26.2 C26.4 C28.2 C28.4 L3.2 R19.2 R20.1 R21.2 R22.1 R23.1 U4.1 U10.2 U11.3 U12.4 U12.6 U13.1 | length 8.2
  Top Layer w0.381: v1(56.642,111.379) 56.652,111.389 U12.4@56.652,112.512
  Bottom Layer w0.381: v1(56.642,111.379) 56.642,106.299 v1(58.039,104.902)
  other v1: 49.149,97.155 49.911,97.155 48.895,97.79 49.53,97.79 50.165,97.79 48.895,98.552 49.53,98.552 50.165,98.552 48.895,99.314 49.53,99.314 50.165,99.314 48.895,100.076 49.53,100.076 50.165,100.076 49.149,100.711 49.911,100.711 40.767,108.839 41.529,108.839 42.291,108.839 43.053,108.839 43.815,108.839 41.148,109.474 41.91,109.474 42.672,109.474 43.434,109.474 44.196,109.474 41.529,110.109 42.291,110.109 43.18,110.109 43.942,110.109
P5: C13.1 C17.2 C18.2 C20.2 C22.2 C27.1 C28.1 C28.3 C29.1 C30.1 C30.3 C32.1 C35.1 L4.2 R25.2 R27.1 R28.2 R29.1 R30.1 U9.1 U13.2 U14.3 U15.1 U17.4 U17.6 | length 7.1
  Top Layer w0.381: U17.4@80,47.762 80,49.012 v1(80.01,49.022)
  Bottom Layer w0.381: v1(79.121,54.483) 80.01,53.594 v1(80.01,49.022)
  other v1: 57.023,49.149 56.388,49.657 58.039,49.657 57.15,49.911 56.388,50.419 57.785,50.419 58.547,50.419 59.309,50.419 57.023,50.673 58.293,51.054 57.531,51.181 59.055,51.181 56.642,51.308 57.15,51.816 57.912,51.816 58.674,51.816 59.563,51.816 69.215,54.737 69.977,54.737 68.58,55.118 69.469,55.499 68.072,55.626 68.834,55.88 55.118,56.134 56.007,56.134 67.945,56.388 68.707,56.642 54.61,56.896 55.372,56.896 56.261,56.896 68.072,57.15 52.451,104.648 51.943,105.41 52.832,105.41 53.467,105.41 51.689,106.172 52.578,107.188 51.816,107.315 53.34,107.442 52.197,107.95 52.959,107.95 53.721,108.077 51.943,108.585 52.578,108.585 53.213,108.585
